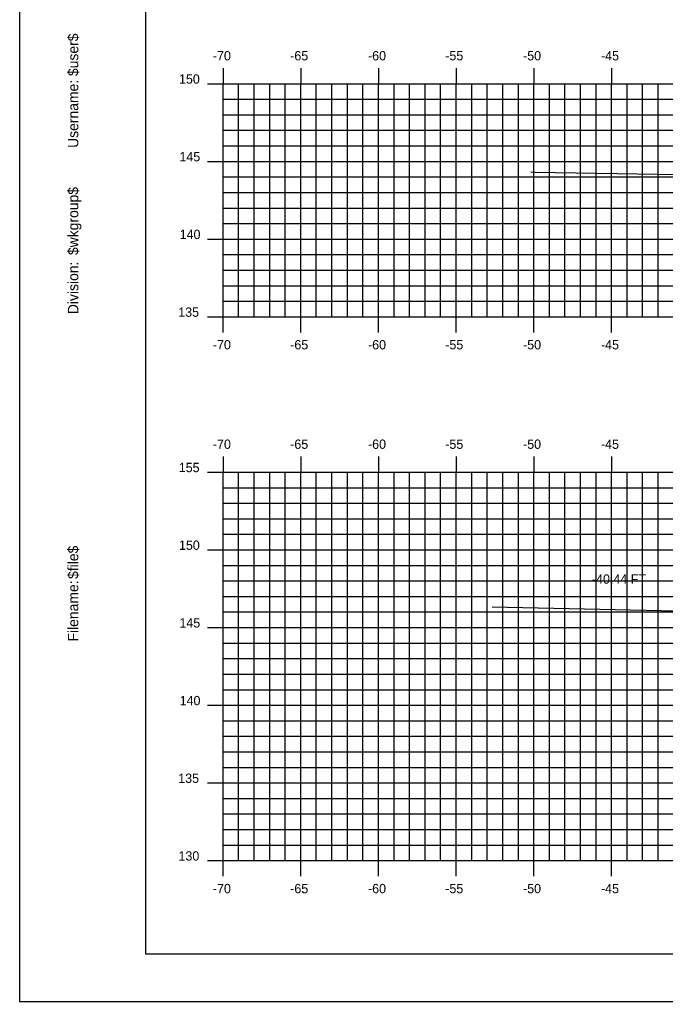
# Model space of a CAD drawing. Extents: x 1144529 to 1144699, y 608981 to 609091.
# Drawn here: x 1144528.8 to 1144570.3, y 608981.3 to 609044.5 of the extents above; entities that cross this region are included whole.
import ezdxf

# ---------------------------------------------------------------- set-up
doc = ezdxf.new("R2010")
doc.units = 0
for name, color, linetype in [('BORDER', 7, 'Continuous'), ('D_Text_Standard', 7, 'Continuous'), ('H_V ANNOTATION', 7, 'Continuous'), ('MAJOR', 7, 'Continuous'), ('MINOR', 7, 'Continuous'), ('PLOT BOUNDARY', 7, 'Continuous'), ('S_Roadway_Centerline', 7, 'Continuous')]:
    doc.layers.add(name, color=color, linetype=linetype)

msp = doc.modelspace()

# ---------------------------------------------------------------- linework, layer by layer
at = {"layer": 'BORDER'}
msp.add_lwpolyline([(1144536.863, 608984.335), (1144696.863, 608984.335), (1144696.863, 609089.335), (1144536.863, 609089.335)], close=True, dxfattribs=at)
at = {"layer": 'MAJOR'}
for p, q in [((1144541.862, 609041.337), (1144541.862, 609040.335)), ((1144546.862, 609041.337), (1144546.862, 609040.335)), ((1144551.862, 609041.337), (1144551.862, 609040.335)), ((1144556.862, 609041.337), (1144556.862, 609040.335)), ((1144561.862, 609041.337), (1144561.862, 609040.335)), ((1144566.862, 609041.337), (1144566.862, 609040.335)), ((1144540.86, 609040.335), (1144541.862, 609040.335)), ((1144541.862, 609040.335), (1144681.862, 609040.335)), ((1144541.862, 609025.335), (1144541.862, 609040.335)), ((1144541.862, 609025.335), (1144541.862, 609040.335)), ((1144541.862, 609040.335), (1144681.862, 609040.335)), ((1144546.862, 609025.335), (1144546.862, 609040.335)), ((1144551.862, 609025.335), (1144551.862, 609040.335)), ((1144556.862, 609025.335), (1144556.862, 609040.335)), ((1144561.862, 609025.335), (1144561.862, 609040.335)), ((1144566.862, 609025.335), (1144566.862, 609040.335)), ((1144540.86, 609035.335), (1144541.862, 609035.335)), ((1144541.862, 609035.335), (1144681.862, 609035.335)), ((1144540.86, 609030.335), (1144541.862, 609030.335)), ((1144541.862, 609030.335), (1144681.862, 609030.335)), ((1144540.86, 609025.335), (1144541.862, 609025.335)), ((1144541.862, 609025.335), (1144681.862, 609025.335)), ((1144541.862, 609025.335), (1144681.862, 609025.335)), ((1144541.862, 609024.333), (1144541.862, 609025.335)), ((1144546.862, 609024.333), (1144546.862, 609025.335)), ((1144551.862, 609024.333), (1144551.862, 609025.335)), ((1144556.862, 609024.333), (1144556.862, 609025.335)), ((1144561.862, 609024.333), (1144561.862, 609025.335)), ((1144566.862, 609024.333), (1144566.862, 609025.335)), ((1144541.862, 609016.337), (1144541.862, 609015.335)), ((1144546.862, 609016.337), (1144546.862, 609015.335)), ((1144551.862, 609016.337), (1144551.862, 609015.335)), ((1144556.862, 609016.337), (1144556.862, 609015.335)), ((1144561.862, 609016.337), (1144561.862, 609015.335)), ((1144566.862, 609016.337), (1144566.862, 609015.335)), ((1144540.86, 609015.335), (1144541.862, 609015.335)), ((1144541.862, 609015.335), (1144681.862, 609015.335)), ((1144541.862, 608990.335), (1144541.862, 609015.335)), ((1144541.862, 608990.335), (1144541.862, 609015.335)), ((1144541.862, 609015.335), (1144681.862, 609015.335)), ((1144546.862, 608990.335), (1144546.862, 609015.335)), ((1144551.862, 608990.335), (1144551.862, 609015.335)), ((1144556.862, 608990.335), (1144556.862, 609015.335)), ((1144561.862, 608990.335), (1144561.862, 609015.335)), ((1144566.862, 608990.335), (1144566.862, 609015.335)), ((1144540.86, 609010.335), (1144541.862, 609010.335)), ((1144541.862, 609010.335), (1144681.862, 609010.335)), ((1144540.86, 609005.335), (1144541.862, 609005.335)), ((1144541.862, 609005.335), (1144681.862, 609005.335)), ((1144540.86, 609000.335), (1144541.862, 609000.335)), ((1144541.862, 609000.335), (1144681.862, 609000.335)), ((1144540.86, 608995.335), (1144541.862, 608995.335)), ((1144541.862, 608995.335), (1144681.862, 608995.335)), ((1144540.86, 608990.335), (1144541.862, 608990.335)), ((1144541.862, 608990.335), (1144681.862, 608990.335)), ((1144541.862, 608990.335), (1144681.862, 608990.335)), ((1144541.862, 608989.333), (1144541.862, 608990.335)), ((1144546.862, 608989.333), (1144546.862, 608990.335)), ((1144551.862, 608989.333), (1144551.862, 608990.335)), ((1144556.862, 608989.333), (1144556.862, 608990.335)), ((1144561.862, 608989.333), (1144561.862, 608990.335)), ((1144566.862, 608989.333), (1144566.862, 608990.335))]:
    msp.add_line(p, q, dxfattribs=at)
at = {"layer": 'MINOR'}
for p, q in [((1144542.862, 609025.335), (1144542.862, 609040.335)), ((1144543.862, 609025.335), (1144543.862, 609040.335)), ((1144544.862, 609025.335), (1144544.862, 609040.335)), ((1144545.862, 609025.335), (1144545.862, 609040.335)), ((1144547.862, 609025.335), (1144547.862, 609040.335)), ((1144548.862, 609025.335), (1144548.862, 609040.335)), ((1144549.862, 609025.335), (1144549.862, 609040.335)), ((1144550.862, 609025.335), (1144550.862, 609040.335)), ((1144552.862, 609025.335), (1144552.862, 609040.335)), ((1144553.862, 609025.335), (1144553.862, 609040.335)), ((1144554.862, 609025.335), (1144554.862, 609040.335)), ((1144555.862, 609025.335), (1144555.862, 609040.335)), ((1144557.862, 609025.335), (1144557.862, 609040.335)), ((1144558.862, 609025.335), (1144558.862, 609040.335)), ((1144559.862, 609025.335), (1144559.862, 609040.335)), ((1144560.862, 609025.335), (1144560.862, 609040.335)), ((1144562.862, 609025.335), (1144562.862, 609040.335)), ((1144563.862, 609025.335), (1144563.862, 609040.335)), ((1144564.862, 609025.335), (1144564.862, 609040.335)), ((1144565.862, 609025.335), (1144565.862, 609040.335)), ((1144567.862, 609025.335), (1144567.862, 609040.335)), ((1144568.862, 609025.335), (1144568.862, 609040.335)), ((1144569.862, 609025.335), (1144569.862, 609040.335)), ((1144541.862, 609039.335), (1144681.862, 609039.335)), ((1144541.862, 609039.335), (1144542.864, 609039.335)), ((1144541.862, 609038.335), (1144681.862, 609038.335)), ((1144541.862, 609038.335), (1144542.864, 609038.335)), ((1144541.862, 609037.335), (1144681.862, 609037.335)), ((1144541.862, 609037.335), (1144542.864, 609037.335)), ((1144541.862, 609036.335), (1144681.862, 609036.335)), ((1144541.862, 609036.335), (1144542.864, 609036.335)), ((1144541.862, 609034.335), (1144681.862, 609034.335)), ((1144541.862, 609034.335), (1144542.864, 609034.335)), ((1144541.862, 609033.335), (1144681.862, 609033.335)), ((1144541.862, 609033.335), (1144542.864, 609033.335)), ((1144541.862, 609032.335), (1144681.862, 609032.335)), ((1144541.862, 609032.335), (1144542.864, 609032.335)), ((1144541.862, 609031.335), (1144681.862, 609031.335)), ((1144541.862, 609031.335), (1144542.864, 609031.335)), ((1144541.862, 609029.335), (1144681.862, 609029.335)), ((1144541.862, 609029.335), (1144542.864, 609029.335)), ((1144541.862, 609028.335), (1144681.862, 609028.335)), ((1144541.862, 609028.335), (1144542.864, 609028.335)), ((1144541.862, 609027.335), (1144681.862, 609027.335)), ((1144541.862, 609027.335), (1144542.864, 609027.335)), ((1144541.862, 609026.335), (1144681.862, 609026.335)), ((1144541.862, 609026.335), (1144542.864, 609026.335)), ((1144542.862, 608990.335), (1144542.862, 609015.335)), ((1144543.862, 608990.335), (1144543.862, 609015.335)), ((1144544.862, 608990.335), (1144544.862, 609015.335)), ((1144545.862, 608990.335), (1144545.862, 609015.335)), ((1144547.862, 608990.335), (1144547.862, 609015.335)), ((1144548.862, 608990.335), (1144548.862, 609015.335)), ((1144549.862, 608990.335), (1144549.862, 609015.335)), ((1144550.862, 608990.335), (1144550.862, 609015.335)), ((1144552.862, 608990.335), (1144552.862, 609015.335)), ((1144553.862, 608990.335), (1144553.862, 609015.335)), ((1144554.862, 608990.335), (1144554.862, 609015.335)), ((1144555.862, 608990.335), (1144555.862, 609015.335)), ((1144557.862, 608990.335), (1144557.862, 609015.335)), ((1144558.862, 608990.335), (1144558.862, 609015.335)), ((1144559.862, 608990.335), (1144559.862, 609015.335)), ((1144560.862, 608990.335), (1144560.862, 609015.335)), ((1144562.862, 608990.335), (1144562.862, 609015.335)), ((1144563.862, 608990.335), (1144563.862, 609015.335)), ((1144564.862, 608990.335), (1144564.862, 609015.335)), ((1144565.862, 608990.335), (1144565.862, 609015.335)), ((1144567.862, 608990.335), (1144567.862, 609015.335)), ((1144568.862, 608990.335), (1144568.862, 609015.335)), ((1144569.862, 608990.335), (1144569.862, 609015.335)), ((1144541.862, 609014.335), (1144681.862, 609014.335)), ((1144541.862, 609014.335), (1144542.864, 609014.335)), ((1144541.862, 609013.335), (1144681.862, 609013.335)), ((1144541.862, 609013.335), (1144542.864, 609013.335)), ((1144541.862, 609012.335), (1144681.862, 609012.335)), ((1144541.862, 609012.335), (1144542.864, 609012.335)), ((1144541.862, 609011.335), (1144681.862, 609011.335)), ((1144541.862, 609011.335), (1144542.864, 609011.335)), ((1144541.862, 609009.335), (1144681.862, 609009.335)), ((1144541.862, 609009.335), (1144542.864, 609009.335)), ((1144541.862, 609008.335), (1144681.862, 609008.335)), ((1144541.862, 609008.335), (1144542.864, 609008.335)), ((1144541.862, 609007.335), (1144681.862, 609007.335)), ((1144541.862, 609007.335), (1144542.864, 609007.335)), ((1144541.862, 609006.335), (1144681.862, 609006.335)), ((1144541.862, 609006.335), (1144542.864, 609006.335)), ((1144541.862, 609004.335), (1144681.862, 609004.335)), ((1144541.862, 609004.335), (1144542.864, 609004.335)), ((1144541.862, 609003.335), (1144681.862, 609003.335)), ((1144541.862, 609003.335), (1144542.864, 609003.335)), ((1144541.862, 609002.335), (1144681.862, 609002.335)), ((1144541.862, 609002.335), (1144542.864, 609002.335)), ((1144541.862, 609001.335), (1144681.862, 609001.335)), ((1144541.862, 609001.335), (1144542.864, 609001.335)), ((1144541.862, 608999.335), (1144681.862, 608999.335)), ((1144541.862, 608999.335), (1144542.864, 608999.335)), ((1144541.862, 608998.335), (1144681.862, 608998.335)), ((1144541.862, 608998.335), (1144542.864, 608998.335)), ((1144541.862, 608997.335), (1144681.862, 608997.335)), ((1144541.862, 608997.335), (1144542.864, 608997.335)), ((1144541.862, 608996.335), (1144681.862, 608996.335)), ((1144541.862, 608996.335), (1144542.864, 608996.335)), ((1144541.862, 608994.335), (1144681.862, 608994.335)), ((1144541.862, 608994.335), (1144542.864, 608994.335)), ((1144541.862, 608993.335), (1144681.862, 608993.335)), ((1144541.862, 608993.335), (1144542.864, 608993.335)), ((1144541.862, 608992.335), (1144681.862, 608992.335)), ((1144541.862, 608992.335), (1144542.864, 608992.335)), ((1144541.862, 608991.335), (1144681.862, 608991.335)), ((1144541.862, 608991.335), (1144542.864, 608991.335))]:
    msp.add_line(p, q, dxfattribs=at)
at = {"layer": 'PLOT BOUNDARY'}
msp.add_lwpolyline([(1144528.769, 608981.276), (1144698.769, 608981.276), (1144698.769, 609091.276), (1144528.769, 609091.276)], close=True, dxfattribs=at)
at = {"layer": 'S_Roadway_Centerline'}
for points in [[(1144561.666, 609034.654), (1144561.946, 609034.651), (1144585.646, 609034.256), (1144592.503, 609033.516), (1144592.567, 609033.501), (1144595.079, 609034.252), (1144595.9, 609034.497), (1144595.906, 609034.498), (1144598.704, 609034.678), (1144598.944, 609034.678), (1144609.518, 609034.918), (1144620.904, 609034.561), (1144621.236, 609034.553), (1144621.437, 609034.537), (1144625.991, 609034.203), (1144626.131, 609034.175), (1144629.717, 609033.462), (1144631.943, 609033.887), (1144632.107, 609033.929), (1144632.595, 609033.902), (1144655.776, 609032.498)], [(1144559.187, 609006.676), (1144578.978, 609006.241), (1144581.605, 609006.146), (1144590.889, 609003.306), (1144592.175, 609002.739), (1144592.604, 609002.838), (1144596.133, 609003.761), (1144597.846, 609003.878), (1144598.337, 609003.906), (1144599.767, 609003.934), (1144609.205, 609003.954), (1144611.065, 609003.88), (1144619.958, 609003.648), (1144620.511, 609003.593), (1144625.858, 609003.18), (1144626.506, 609003.065), (1144628.858, 609002.594), (1144634.039, 609003.929), (1144635.609, 609003.813), (1144637.17, 609003.769), (1144654.147, 609002.813), (1144656.428, 609002.61), (1144659.014, 609002.64)]]:
    msp.add_lwpolyline(points, dxfattribs=at)

# ---------------------------------------------------------------- texts
at = {"layer": 'BORDER'}
for s, p in [('$user$', (1144532.547, 609040.827)), ('Username:', (1144532.547, 609036.203)), ('$wkgroup$', (1144532.547, 609029.305)), ('Division:', (1144532.547, 609025.501)), ('$file$', (1144532.547, 609008.461)), ('Filename:', (1144532.547, 609004.433))]:
    msp.add_text(s, height=0.6696, rotation=90, dxfattribs=at).set_placement(p)
at = {"layer": 'D_Text_Standard'}
msp.add_text('-40.44 FT', height=0.6, dxfattribs=at).set_placement((1144565.597, 609008.155))
at = {"layer": 'H_V ANNOTATION'}
for s, p in [('-70', (1144541.204, 609041.835)), ('-65', (1144546.18, 609041.835)), ('-60', (1144551.188, 609041.835)), ('-55', (1144556.158, 609041.835)), ('-50', (1144561.167, 609041.835)), ('-45', (1144566.18, 609041.835)), ('150', (1144539.024, 609040.335)), ('145', (1144539.051, 609035.335)), ('140', (1144539.067, 609030.335)), ('135', (1144538.976, 609025.335)), ('-70', (1144541.204, 609023.235)), ('-65', (1144546.18, 609023.235)), ('-60', (1144551.188, 609023.235)), ('-55', (1144556.158, 609023.235)), ('-50', (1144561.167, 609023.235)), ('-45', (1144566.18, 609023.235)), ('-70', (1144541.204, 609016.835)), ('-65', (1144546.18, 609016.835)), ('-60', (1144551.188, 609016.835)), ('-55', (1144556.158, 609016.835)), ('-50', (1144561.167, 609016.835)), ('-45', (1144566.18, 609016.835)), ('155', (1144539.008, 609015.335)), ('150', (1144539.024, 609010.335)), ('145', (1144539.051, 609005.335)), ('140', (1144539.067, 609000.335)), ('135', (1144538.976, 608995.335)), ('130', (1144538.992, 608990.335)), ('-70', (1144541.204, 608988.235)), ('-65', (1144546.18, 608988.235)), ('-60', (1144551.188, 608988.235)), ('-55', (1144556.158, 608988.235)), ('-50', (1144561.167, 608988.235)), ('-45', (1144566.18, 608988.235))]:
    msp.add_text(s, height=0.6, dxfattribs=at).set_placement(p)
at = {"layer": 'MAJOR'}
for p in [(1144541.858, 609025.335), (1144541.858, 608990.335)]:
    msp.add_text('-', height=0.006, dxfattribs=at).set_placement(p)

doc.saveas('drawing.dxf')
